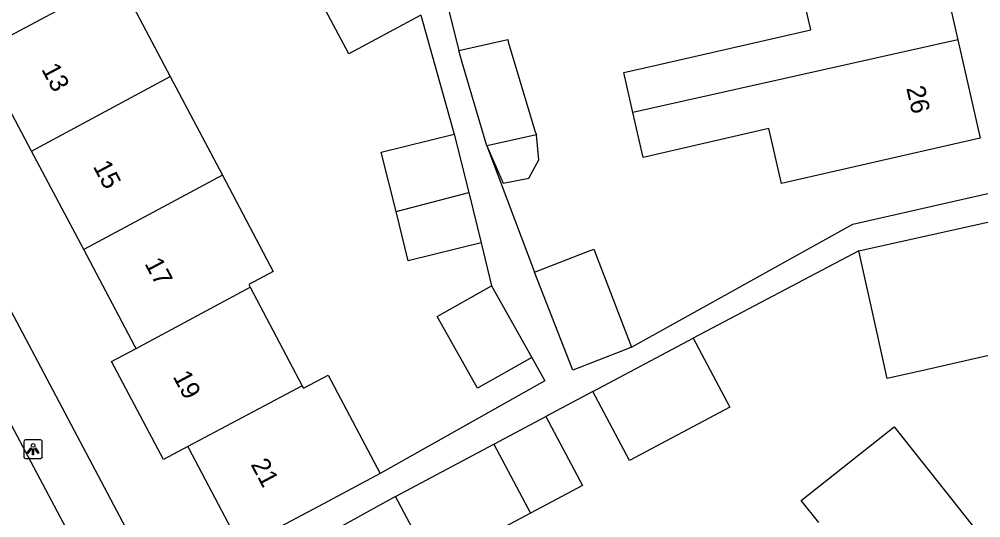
# Model space of a CAD drawing. Extents: x 157321 to 158827, y 386650 to 388532.
# Drawn here: x 157729.7 to 157781.4, y 387598.8 to 387625.6 of the extents above; entities that cross this region are included whole.
import ezdxf

# ---------------------------------------------------------------- set-up
doc = ezdxf.new("R2010")
doc.units = 0
for name, color, linetype in [('IMGEO_Lichtpunt', 7, 'Continuous'), ('IMGEO_Pand', 7, 'Continuous'), ('IMGEO_Pand_nummerreeks', 7, 'Continuous'), ('IMGEO_Rijbaan_lokaal_open', 7, 'Continuous'), ('IMGEO_Voetpad_open', 7, 'Continuous')]:
    doc.layers.add(name, color=color, linetype=linetype)

msp = doc.modelspace()

# ---------------------------------------------------------------- linework, layer by layer
at = {"layer": 'IMGEO_Lichtpunt'}
for p, q in [((157729.914, 387602.924), (157729.914, 387602.117)), ((157729.914, 387602.924), (157729.914, 387602.117)), ((157730.816, 387603.019), (157730.008, 387603.019)), ((157730.816, 387603.019), (157730.008, 387603.019)), ((157730.91, 387602.117), (157730.91, 387602.924)), ((157730.91, 387602.117), (157730.91, 387602.924)), ((157730.008, 387602.023), (157730.816, 387602.023)), ((157730.008, 387602.023), (157730.816, 387602.023))]:
    msp.add_line(p, q, dxfattribs=at)
for points in [[(157730.288, 387602.588), (157730.327, 387602.56), (157730.139, 387602.298), (157730.101, 387602.325), (157730.288, 387602.588)], [(157730.39, 387602.54), (157730.437, 387602.54), (157730.437, 387602.218), (157730.39, 387602.218), (157730.39, 387602.54)], [(157730.5, 387602.56), (157730.538, 387602.587), (157730.725, 387602.325), (157730.686, 387602.297), (157730.5, 387602.56)]]:
    msp.add_lwpolyline(points, dxfattribs=at)
msp.add_circle((157730.413, 387602.722), 0.0994, dxfattribs=at)
for centre, start, end in [((157730.008, 387602.924), 90, 180), ((157730.008, 387602.924), 90, 180), ((157730.816, 387602.924), 0, 90), ((157730.816, 387602.924), 0, 90), ((157730.008, 387602.117), 180, 270), ((157730.008, 387602.117), 180, 270), ((157730.816, 387602.117), 270, 0), ((157730.816, 387602.117), 270, 360)]:
    msp.add_arc(centre, 0.0946, start, end, dxfattribs=at)
at = {"layer": 'IMGEO_Pand'}
for points in [[(157778.953, 387629.697), (157780.136, 387624.527)], [(157727.501, 387623.859), (157734.991, 387627.855)], [(157734.991, 387627.855), (157737.792, 387622.555)], [(157762.671, 387620.612), (157762.184, 387622.763), (157763.85, 387623.14), (157772.232, 387625.059), (157771.559, 387628)], [(157751.256, 387625.843), (157747.39, 387623.77), (157745.862, 387626.619)], [(157753.316, 387623.956), (157755.938, 387624.537), (157755.969, 387624.415), (157757.392, 387619.632), (157757.483, 387619.418)], [(157780.136, 387624.527), (157781.345, 387619.246), (157776.472, 387618.131), (157770.66, 387616.8), (157769.985, 387619.751), (157763.216, 387618.202), (157762.671, 387620.612)], [(157780.136, 387624.527), (157762.671, 387620.612)], [(157754.815, 387618.826), (157753.481, 387623.31), (157753.316, 387623.956)], [(157730.322, 387618.545), (157727.568, 387623.732), (157727.501, 387623.859)], [(157730.322, 387618.545), (157737.792, 387622.555)], [(157737.792, 387622.555), (157740.593, 387617.255)], [(157749.929, 387615.29), (157749.137, 387618.489), (157753.062, 387619.46)], [(157753.062, 387619.46), (157753.84, 387616.318)], [(157757.483, 387619.418), (157754.815, 387618.826)], [(157754.815, 387618.826), (157755.692, 387616.814), (157757.067, 387617.094), (157757.614, 387618.08), (157757.483, 387619.418)], [(157733.136, 387613.247), (157730.322, 387618.545)], [(157740.593, 387617.255), (157733.136, 387613.247)], [(157740.593, 387617.255), (157743.332, 387612.073), (157742.006, 387611.373), (157742.078, 387611.236)], [(157749.929, 387615.29), (157753.84, 387616.318)], [(157753.84, 387616.318), (157754.509, 387613.614)], [(157754.509, 387613.614), (157750.585, 387612.643), (157749.929, 387615.29)], [(157782.315, 387614.847), (157783.86, 387608.02), (157778.515, 387606.81), (157776.348, 387606.319), (157775.724, 387609.077), (157774.811, 387613.18)], [(157774.811, 387613.18), (157782.315, 387614.847)], [(157735.954, 387607.939), (157735.893, 387608.055), (157733.136, 387613.247)], [(157757.37, 387612.04), (157760.131, 387613.106), (157760.562, 387613.272), (157762.596, 387608.005)], [(157762.596, 387608.005), (157762.194, 387607.85), (157759.439, 387606.769), (157757.37, 387612.04)], [(157735.954, 387607.939), (157742.078, 387611.236)], [(157742.078, 387611.236), (157744.881, 387605.934)], [(157757.231, 387607.453), (157754.306, 387605.806), (157752.142, 387609.65), (157755.067, 387611.296)], [(157755.067, 387611.296), (157757.231, 387607.453)], [(157765.901, 387608.491), (157767.874, 387604.783), (157762.488, 387601.918), (157760.516, 387605.626)], [(157760.516, 387605.626), (157765.901, 387608.491)], [(157738.734, 387602.661), (157737.424, 387601.963), (157734.629, 387607.226), (157735.954, 387607.939)], [(157744.881, 387605.934), (157744.95, 387605.803), (157746.276, 387606.503), (157749.074, 387601.207)], [(157744.881, 387605.934), (157738.734, 387602.661)], [(157755.192, 387602.794), (157757.982, 387604.278)], [(157757.982, 387604.278), (157759.954, 387600.57), (157757.164, 387599.086)], [(157772.66, 387598.584), (157771.725, 387599.764), (157776.721, 387603.721), (157778.652, 387601.283), (157783.851, 387594.721), (157783.987, 387594.549), (157780.761, 387591.993), (157779.111, 387590.686)], [(157749.895, 387599.976), (157752.393, 387601.305), (157755.192, 387602.794)], [(157755.192, 387602.794), (157757.164, 387599.086)], [(157741.611, 387597.243), (157738.8, 387602.537), (157738.734, 387602.661)], [(157749.074, 387601.207), (157746.027, 387599.589), (157741.611, 387597.243)], [(157757.164, 387599.086), (157754.366, 387597.597), (157751.867, 387596.268), (157749.895, 387599.976)]]:
    msp.add_lwpolyline(points, dxfattribs=at)
at = {"layer": 'IMGEO_Rijbaan_lokaal_open'}
msp.add_lwpolyline([(157735.466, 387592.089), (157729.998, 387602.392), (157713.019, 387634.314), (157706.841, 387645.947), (157703.178, 387652.824)], dxfattribs=at)
at = {"layer": 'IMGEO_Voetpad_open'}
for points in [[(157705.154, 387655.407), (157705.212, 387655.297), (157737.182, 387594.934), (157737.199, 387594.901)], [(157752.735, 387626.222), (157753.316, 387623.956)], [(157751.256, 387625.843), (157753.062, 387619.46)], [(157754.815, 387618.826), (157757.37, 387612.04)], [(157762.596, 387608.005), (157774.491, 387614.619), (157786.883, 387617.427)], [(157754.509, 387613.614), (157755.067, 387611.296)], [(157774.811, 387613.18), (157765.901, 387608.491)], [(157757.231, 387607.453), (157757.938, 387606.198), (157749.074, 387601.207)], [(157760.516, 387605.626), (157757.982, 387604.278)], [(157749.895, 387599.976), (157746.825, 387598.27)]]:
    msp.add_lwpolyline(points, dxfattribs=at)

# ---------------------------------------------------------------- texts
at = {"layer": 'IMGEO_Pand_nummerreeks'}
for s, rotation, p in [('13', 297.9716, (157730.837, 387622.95)), ('26', 282.8933, (157777.365, 387621.938)), ('15', 297.9698, (157733.612, 387617.725)), ('17', 297.9716, (157736.387, 387612.499)), ('19', 297.9716, (157737.908, 387606.426)), ('21', 297.9659, (157742.097, 387601.703))]:
    msp.add_text(s, height=1, rotation=rotation, dxfattribs=at).set_placement(p)

doc.saveas('drawing.dxf')
